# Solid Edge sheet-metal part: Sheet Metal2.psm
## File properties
Author: Priit
Template: Normal.psm
Last saved by: Priit
Revision: 1
Application: Solid Edge
Accuracy: 0,990
Material Thickness: 1,00 mm
Bend Radius: 1,00 mm
Relief Width: 1,00 mm
Relief Length: 0,00 mm
Neutral Factor: 0,330
Minimum Arc Length: 0,10 mm
Deviational Tolerance: 0,10 mm
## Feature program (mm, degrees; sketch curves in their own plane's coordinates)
base tab "unnamed BaseTab 1"
flange "Flange_1"
flange "Flange_2"
flange "Flange_3"
sketch for "ExtrudedCutout_1" plane through (-15, -10, -2.3319) normal (-1, 0, 0) x-axis (0, -1, 0)
  bspline degree 3 poles (7.4997, -0.2296) (6.7472, -0.0124) (4.6415, 0.7336) (1.1119, -2.1766) (-2.9988, 0.8044) (-5.6703, 0.1647) (-7.2191, -0.051) knots 0 0.141 0.4463 0.7185 1 multiplicities 4 1 1 1 4
  bspline degree 3 poles (-7.2191, -0.051) (-5.6311, 0.5279) (-2.9653, 1.7343) (1.0834, -0.6783) (4.6671, 1.6415) (6.6124, 0.3254) (7.4997, -0.2296) knots 0 0.3018 0.5619 0.8131 1 multiplicities 4 1 1 1 4
extrude "ExtrudedCutout_1" cut
sketch for "Hole_1" plane through (-7.5, -11, 1) normal (0, 0, 1) x-axis (1, 0, 0)
  hole centre (0.1742, -4.7032) bore radius 3.175
hole "Hole_1"
dimple "Dimple_2"
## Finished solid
Body 1: solid body, 37 faces, 84 edges, 48 vertices.
  Faces by surface: plane 22, cylinder 9, swept 4, torus 2
  Edges by curve: line 56, circle 20, spline 8
Bounding box of the edges (mm; curved faces can reach further): 15.000 x 20.000 x 8.651, from (-15, -20, -3.7878) to (0, 0, 4.8631).
Cylindrical faces by radius (mm): R0.168 x1, R1 x3, R1.168 x1, R2 x3, R3.175 x1
Toroidal faces (ring radius, tube radius in mm): R0.168 r1 x1, R1.168 r1 x1
Planar faces by outward normal: +x 4, +y 5, +z 3, -x 4, -y 2, -z 4
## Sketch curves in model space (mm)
circle centre (-7.6394, -8.4219, 1) radius 1.168
circle centre (-4.6084, -4.0323, 1) radius 0.9381
circle centre (-11.2277, -4.0323, 1) radius 0.9811
line (-12.2032, -19.3265, 1) -> (-3.0406, -19.3265, 1)
line (-3.0406, -19.3265, 1) -> (-3.0406, -20, 1)
line (-3.0406, -20, 1) -> (-12.2032, -20, 1)
line (-12.2032, -20, 1) -> (-12.2032, -19.3265, 1)
spline (-15, -17.4997, -2.5615) -> (-15, -10.191, -3.3403) -> (-15, -2.7809, -2.3829)
spline (-15, -2.7809, -2.3829) -> (-15, -10.2123, -2.1256) -> (-15, -17.4997, -2.5615)
line (-15, 0, 0) -> (-15, -20, 0)
line (-15, -20, 0) -> (0, -20, 0)
line (0, -20, 0) -> (0, 0, 0)
line (0, 0, 0) -> (-15, 0, 0)
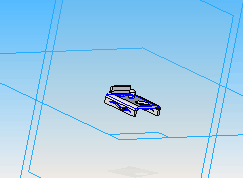
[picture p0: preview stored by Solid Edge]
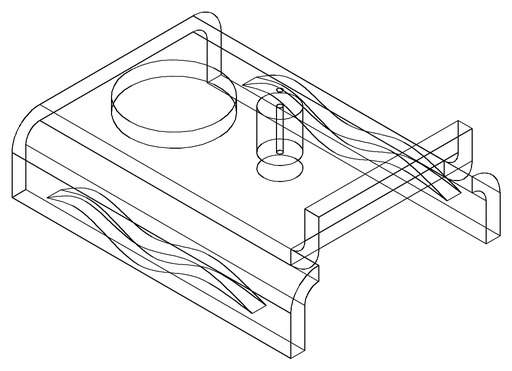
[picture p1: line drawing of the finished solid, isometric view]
